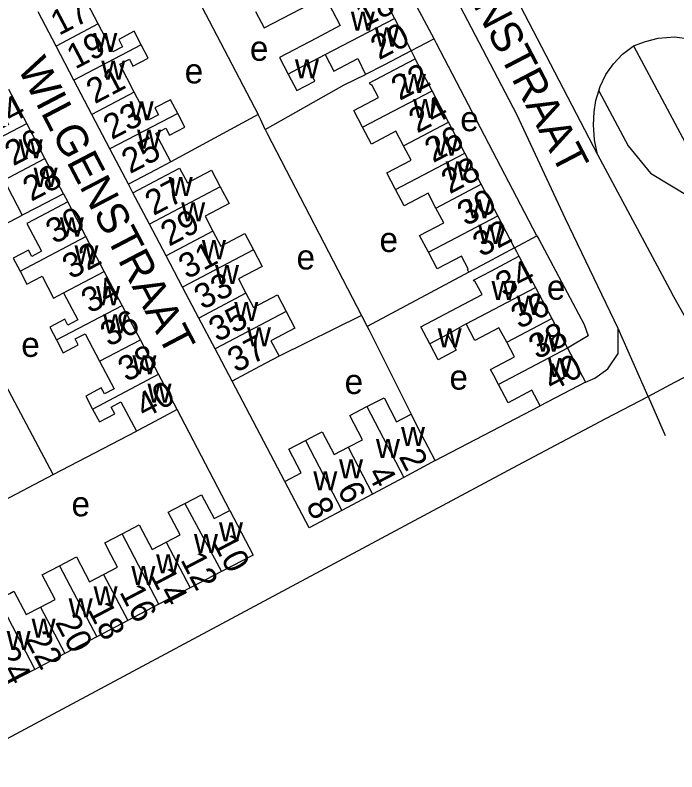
# Model space of a CAD drawing. Extents: x 158356 to 159894, y 383831 to 385260.
# Drawn here: x 159379.2 to 159485.7, y 384265.1 to 384387 of the extents above; entities that cross this region are included whole.
import ezdxf

# ---------------------------------------------------------------- set-up
doc = ezdxf.new("R2010")
doc.units = 0
for name, color, linetype in [('BLT_Basislijn', 7, 'Continuous'), ('BLT_Bebouwing', 7, 'Continuous'), ('BLT_Centroide', 7, 'Continuous'), ('BLT_Huisnummer', 7, 'Continuous'), ('BLT_Huisnummer_ tussenligend', 7, 'Continuous'), ('BLT_Onderverdeling_panden', 7, 'Continuous'), ('BLT_Straatnaam', 7, 'Continuous'), ('BLT_Vlakafsluiter', 7, 'Continuous')]:
    doc.layers.add(name, color=color, linetype=linetype)

msp = doc.modelspace()

# ---------------------------------------------------------------- linework, layer by layer
at = {"layer": 'BLT_Basislijn'}
for p, q in [((159446.66, 384383.13), (159442.98, 384381.23)), ((159478.78, 384382.01), (159487.1, 384366.47)), ((159442.98, 384381.23), (159443.63, 384379.92)), ((159418.33, 384370.96), (159404.29, 384363.33)), ((159398.17, 384358.36), (159397.45, 384359.74)), ((159386.98, 384358.21), (159387.68, 384356.87)), ((159366.92, 384347.68), (159380.36, 384354.74)), ((159459.62, 384349.47), (159463.22, 384351.41)), ((159459.62, 384349.47), (159459.91, 384348.91)), ((159459.91, 384348.91), (159460.33, 384348.14)), ((159452.24, 384345.59), (159435.89, 384336.82)), ((159434.96, 384338.58), (159421.72, 384332.02)), ((159434.96, 384338.58), (159435.89, 384336.82)), ((159485.42, 384327.84), (159493.7, 384332.21)), ((159422.61, 384311.87), (159414.14, 384328.02)), ((159446.84, 384315.22), (159463.76, 384324.01)), ((159413.77, 384307.19), (159405.3, 384323.43)), ((159385.33, 384312.96), (159398.73, 384319.97)), ((159423.05, 384294.6), (159460.13, 384314.46)), ((159371.64, 384305.8), (159385.33, 384312.96)), ((159367.92, 384265.07), (159423.05, 384294.6))]:
    msp.add_line(p, q, dxfattribs=at)
for points in [[(159476.29, 384336.47), (159467.84, 384354.16), (159459.96, 384370.94), (159444.22, 384401.18), (159439.12, 384409.82), (159405.78, 384459.91), (159379.56, 384494.51), (159361.43, 384512.52)], [(159446.66, 384383.13), (159439.98, 384395.74), (159434.84, 384404.77), (159434.31, 384405.59)], [(159408.42, 384390.03), (159408.65, 384389.59), (159418.33, 384370.96)], [(159478.78, 384382.01), (159480.69, 384382.71), (159482.75, 384383.26), (159485.41, 384383.46), (159487.73, 384383.17), (159490.35, 384382.47), (159493.66, 384380.96), (159534.17, 384359.27)], [(159463.22, 384351.41), (159447.05, 384382.38), (159446.66, 384383.13)], [(159473.16, 384374.75), (159473.38, 384375.49), (159474.32, 384377.4), (159475.56, 384379.13), (159476.99, 384380.7), (159478.69, 384381.98), (159478.78, 384382.01)], [(159419.48, 384368.57), (159432.2, 384375.73), (159435.63, 384377.4)], [(159472.97, 384364.5), (159472.47, 384366.87), (159472.31, 384369.29), (159472.41, 384371.42), (159472.73, 384373.24), (159473.16, 384374.75)], [(159473.16, 384374.75), (159477.91, 384365.91), (159481.52, 384361.49), (159488.02, 384357.59)], [(159419.48, 384368.57), (159418.76, 384370.12), (159418.33, 384370.96)], [(159419.48, 384368.57), (159419.78, 384367.92), (159434.96, 384338.58)], [(159472.97, 384364.5), (159484.97, 384342.1)], [(159463.22, 384351.41), (159463.51, 384350.86), (159470.83, 384337.11), (159471.45, 384335.29), (159468.16, 384333.32)], [(159385.33, 384312.96), (159367.27, 384347.02), (159366.92, 384347.68)], [(159491.46, 384336.44), (159488.92, 384335.09), (159484.97, 384342.1)], [(159435.89, 384336.82), (159436.15, 384336.33), (159442.96, 384322.7)], [(159472.53, 384328.48), (159474.64, 384329.97), (159476.29, 384332.49), (159476.29, 384336.47)], [(159471.04, 384327.86), (159472.53, 384328.48)], [(159481.11, 384325.55), (159485.42, 384327.84)], [(159474.33, 384321.97), (159481.11, 384325.55)], [(159460.13, 384314.46), (159474.33, 384321.97)]]:
    msp.add_lwpolyline(points, dxfattribs=at)
at = {"layer": 'BLT_Bebouwing'}
for p, q in [((159437.65, 384391.47), (159440.27, 384386.42)), ((159385.8, 384381.99), (159382.9, 384387.52)), ((159440.27, 384386.42), (159442.98, 384381.23)), ((159388.66, 384376.52), (159385.8, 384381.99)), ((159446.33, 384374.78), (159443.63, 384379.92)), ((159391.56, 384370.99), (159388.66, 384376.52)), ((159381.07, 384369.5), (159378.18, 384375)), ((159448.97, 384369.75), (159446.33, 384374.78)), ((159394.47, 384365.43), (159391.56, 384370.99)), ((159384.02, 384363.87), (159381.07, 384369.5)), ((159451.59, 384364.76), (159448.97, 384369.75)), ((159397.45, 384359.74), (159394.47, 384365.43)), ((159386.98, 384358.21), (159384.02, 384363.87)), ((159454.24, 384359.72), (159451.59, 384364.76)), ((159456.9, 384354.65), (159454.24, 384359.72)), ((159400.83, 384353.3), (159398.17, 384358.36)), ((159390.6, 384351.32), (159387.68, 384356.87)), ((159459.62, 384349.47), (159456.9, 384354.65)), ((159403.52, 384348.19), (159400.83, 384353.3)), ((159393.57, 384345.69), (159390.6, 384351.32)), ((159406.18, 384343.13), (159403.52, 384348.19)), ((159460.33, 384348.14), (159462.98, 384343.11)), ((159396.45, 384340.21), (159393.57, 384345.69)), ((159408.79, 384338.18), (159406.18, 384343.13)), ((159462.98, 384343.11), (159465.62, 384338.11)), ((159399.37, 384334.68), (159396.45, 384340.21)), ((159411.41, 384333.2), (159408.79, 384338.18)), ((159465.62, 384338.11), (159468.16, 384333.32)), ((159402.3, 384329.12), (159399.37, 384334.68)), ((159468.16, 384333.32), (159471.04, 384327.86)), ((159414.14, 384328.02), (159411.41, 384333.2)), ((159405.3, 384323.43), (159402.3, 384329.12)), ((159471.04, 384327.86), (159463.76, 384324.01)), ((159446.84, 384315.22), (159441.77, 384312.51)), ((159441.77, 384312.51), (159436.76, 384309.83)), ((159436.76, 384309.83), (159431.81, 384307.19)), ((159412.46, 384297.35), (159407.39, 384294.7)), ((159407.39, 384294.7), (159402.37, 384292.07)), ((159402.37, 384292.07), (159397.35, 384289.44)), ((159397.35, 384289.44), (159392.34, 384286.82)), ((159392.34, 384286.82), (159387.24, 384284.15)), ((159387.24, 384284.15), (159382.36, 384281.59))]:
    msp.add_line(p, q, dxfattribs=at)
for points in [[(159392.59, 384385.55), (159390.25, 384390.02), (159391.77, 384390.81), (159392.32, 384389.77), (159394.8, 384391.07), (159393.7, 384393.17)], [(159417.9, 384387.57), (159419.29, 384384.91), (159425.21, 384388), (159429.08, 384390.02), (159430.32, 384387.65)], [(159430.32, 384387.65), (159431.55, 384385.28), (159427.73, 384383.28), (159421.76, 384380.17), (159423.17, 384377.46)], [(159399.52, 384382.21), (159398.39, 384384.37), (159395.89, 384383.06), (159396.5, 384381.89), (159394.94, 384381.07), (159392.59, 384385.55)], [(159398.4, 384374.57), (159396.06, 384379.05), (159397.6, 384379.86), (159398.17, 384378.75), (159400.65, 384380.05), (159399.52, 384382.21)], [(159442.98, 384381.23), (159438.55, 384378.92), (159435.63, 384377.4)], [(159426.18, 384379.06), (159429.12, 384380.61)], [(159429.12, 384380.61), (159430.51, 384377.94), (159434.41, 384379.97), (159435.63, 384377.4)], [(159435.15, 384368.91), (159433.73, 384371.61), (159437.71, 384373.7), (159436.63, 384375.76), (159436.46, 384375.67), (159436.26, 384376.05), (159439.21, 384377.6), (159443.63, 384379.92)], [(159423.17, 384377.46), (159424.54, 384374.83), (159427.44, 384376.34), (159426.18, 384379.06)], [(159405.38, 384371.15), (159404.23, 384373.35), (159401.72, 384372.04), (159402.31, 384370.92), (159400.74, 384370.1), (159398.4, 384374.57)], [(159404.29, 384363.33), (159401.88, 384367.93), (159403.46, 384368.76), (159404.05, 384367.64), (159406.53, 384368.95), (159405.38, 384371.15)], [(159441.72, 384365.94), (159440.5, 384368.28), (159436.57, 384366.21), (159435.15, 384368.91)], [(159440.43, 384358.9), (159439.04, 384361.56), (159442.95, 384363.61), (159441.72, 384365.94)], [(159404.29, 384363.33), (159401.88, 384362.06), (159397.45, 384359.74)], [(159398.17, 384358.36), (159402.59, 384360.69), (159405.7, 384362.32), (159406.95, 384359.95), (159410.83, 384361.99), (159412.24, 384359.3)], [(159373.35, 384358.28), (159374.46, 384356.16), (159377, 384357.49), (159376.41, 384358.62), (159377.92, 384359.41), (159380.36, 384354.74)], [(159412.24, 384359.3), (159413.66, 384356.61), (159409.78, 384354.57), (159411.05, 384352.16)], [(159446.96, 384355.9), (159445.71, 384358.29), (159441.83, 384356.24), (159440.43, 384358.9)], [(159386.98, 384358.21), (159382.56, 384355.89), (159380.36, 384354.74)], [(159387.68, 384356.87), (159383.25, 384354.54), (159381.12, 384353.42), (159383.48, 384348.95), (159381.88, 384348.11), (159381.35, 384349.11), (159378.9, 384347.82), (159380, 384345.73)], [(159445.74, 384348.79), (159444.33, 384351.48), (159448.21, 384353.52), (159446.96, 384355.9)], [(159411.05, 384352.16), (159412.32, 384349.74), (159416.21, 384351.79), (159417.61, 384349.14)], [(159417.61, 384349.14), (159419, 384346.5), (159415.16, 384344.48), (159416.38, 384342.17)], [(159459.62, 384349.47), (159455.19, 384347.14), (159452.24, 384345.59)], [(159445.98, 384334), (159444.53, 384336.74), (159450.43, 384339.86), (159454.38, 384341.95), (159453.24, 384344.1), (159453.12, 384344.04), (159453, 384344.26), (159455.91, 384345.8), (159460.33, 384348.14)], [(159452.24, 384345.59), (159452.03, 384345.99), (159452.17, 384346.08), (159451.08, 384348.17), (159447.15, 384346.11), (159445.74, 384348.79)], [(159380, 384345.73), (159381.1, 384343.65), (159383.54, 384344.93), (159385.41, 384341.39), (159387.02, 384342.24)], [(159387.02, 384342.24), (159389.3, 384337.9), (159387.69, 384337.05), (159387.21, 384337.97), (159384.79, 384336.69), (159385.87, 384334.64)], [(159416.38, 384342.17), (159417.59, 384339.87), (159421.43, 384341.89), (159422.84, 384339.22)], [(159422.84, 384339.22), (159424.25, 384336.54), (159420.4, 384334.52), (159421.72, 384332.02)], [(159451.83, 384337.22), (159448.83, 384335.55)], [(159458.36, 384334.27), (159457.11, 384336.62), (159453.23, 384334.57), (159451.83, 384337.22)], [(159385.87, 384334.64), (159386.95, 384332.59), (159389.38, 384333.87), (159388.88, 384334.82), (159390.47, 384335.66), (159392.81, 384331.22)], [(159448.83, 384335.55), (159450.21, 384332.98), (159447.33, 384331.45), (159445.98, 384334)], [(159457.05, 384327.45), (159456.26, 384328.94), (159455.76, 384329.88), (159459.6, 384331.91), (159458.36, 384334.27)], [(159421.72, 384332.02), (159418.56, 384330.35), (159414.14, 384328.02)], [(159392.81, 384331.22), (159395.15, 384326.79), (159393.58, 384325.96), (159393.08, 384326.91), (159390.59, 384325.6), (159391.68, 384323.52)], [(159463.76, 384324.01), (159462.42, 384326.54), (159458.6, 384324.52), (159457.05, 384327.45)], [(159435.85, 384323.92), (159438.62, 384325.35), (159440.62, 384321.48), (159442.96, 384322.7)], [(159391.68, 384323.52), (159392.77, 384321.45), (159395.26, 384322.75), (159394.68, 384323.84), (159396.25, 384324.67), (159398.73, 384319.97)], [(159432.84, 384317.39), (159435.12, 384318.57), (159433.09, 384322.48), (159435.85, 384323.92)], [(159405.3, 384323.43), (159400.88, 384321.1), (159398.73, 384319.97)], [(159446.84, 384315.22), (159444.6, 384319.54), (159442.96, 384322.7)], [(159425.96, 384318.47), (159427.7, 384319.38), (159428.65, 384319.87), (159430.56, 384316.2), (159432.84, 384317.39)], [(159422.61, 384311.87), (159425.25, 384313.24), (159423.26, 384317.07), (159425.96, 384318.47)], [(159431.81, 384307.19), (159426.55, 384304.38), (159422.61, 384311.87)], [(159406.53, 384308.32), (159409.21, 384309.72), (159411.23, 384305.86), (159413.77, 384307.19)], [(159403.54, 384302.05), (159405.79, 384303.23), (159403.86, 384306.92), (159404.78, 384307.4), (159406.53, 384308.32)], [(159413.77, 384307.19), (159417.53, 384300), (159412.46, 384297.35)], [(159396.43, 384303.4), (159399.2, 384304.84), (159401.28, 384300.87), (159403.54, 384302.05)], [(159393.46, 384296.87), (159395.71, 384298.05), (159394.69, 384300), (159393.67, 384301.95), (159396.43, 384303.4)], [(159386.34, 384298.28), (159389.1, 384299.73), (159391.21, 384295.69), (159393.46, 384296.87)], [(159383.32, 384291.62), (159385.66, 384292.85), (159383.58, 384296.83), (159386.34, 384298.28)], [(159376.47, 384292.83), (159378.37, 384293.82), (159379.01, 384294.16), (159380.99, 384290.4), (159383.32, 384291.62)], [(159382.36, 384281.59), (159377.19, 384278.88), (159373.34, 384286.22)]]:
    msp.add_lwpolyline(points, dxfattribs=at)
at = {"layer": 'BLT_Onderverdeling_panden'}
for p, q in [((159429.12, 384380.61), (159440.27, 384386.42)), ((159392.59, 384385.55), (159385.8, 384381.99)), ((159399.52, 384382.21), (159388.66, 384376.52)), ((159426.18, 384379.06), (159423.17, 384377.46)), ((159435.15, 384368.91), (159446.33, 384374.78)), ((159398.4, 384374.57), (159391.56, 384370.99)), ((159405.38, 384371.15), (159394.47, 384365.43)), ((159374.46, 384366.03), (159381.07, 384369.5)), ((159441.72, 384365.94), (159448.97, 384369.75)), ((159373.35, 384358.28), (159384.02, 384363.87)), ((159440.43, 384358.9), (159451.59, 384364.76)), ((159412.24, 384359.3), (159400.83, 384353.3)), ((159446.96, 384355.9), (159454.24, 384359.72)), ((159445.74, 384348.79), (159456.9, 384354.65)), ((159411.05, 384352.16), (159403.52, 384348.19)), ((159380, 384345.73), (159390.6, 384351.32)), ((159417.61, 384349.14), (159406.18, 384343.13)), ((159387.02, 384342.24), (159393.57, 384345.69)), ((159451.83, 384337.22), (159462.98, 384343.11)), ((159416.38, 384342.17), (159408.79, 384338.18)), ((159385.87, 384334.64), (159396.45, 384340.21)), ((159422.84, 384339.22), (159411.41, 384333.2)), ((159458.36, 384334.27), (159465.62, 384338.11)), ((159392.81, 384331.22), (159399.37, 384334.68)), ((159448.83, 384335.55), (159445.98, 384334)), ((159468.16, 384333.32), (159457.05, 384327.45)), ((159391.68, 384323.52), (159402.3, 384329.12)), ((159435.85, 384323.92), (159441.77, 384312.51)), ((159425.96, 384318.47), (159431.81, 384307.19)), ((159432.84, 384317.39), (159436.76, 384309.83)), ((159406.53, 384308.32), (159412.46, 384297.35)), ((159402.37, 384292.07), (159396.43, 384303.4)), ((159403.54, 384302.05), (159407.39, 384294.7)), ((159386.34, 384298.28), (159392.34, 384286.82)), ((159393.46, 384296.87), (159397.35, 384289.44)), ((159376.47, 384292.83), (159382.36, 384281.59)), ((159383.32, 384291.62), (159387.24, 384284.15))]:
    msp.add_line(p, q, dxfattribs=at)
at = {"layer": 'BLT_Vlakafsluiter'}
for p, q in [((159457.18, 384394.95), (159472.97, 384364.5)), ((159481.11, 384325.55), (159476.29, 384336.47)), ((159481.11, 384325.55), (159483.88, 384319.27))]:
    msp.add_line(p, q, dxfattribs=at)

# ---------------------------------------------------------------- texts
at = {"layer": 'BLT_Centroide'}
for s, p in [('w', (159433.26, 384384.47)), ('w', (159437.12, 384381.91)), ('w', (159391.79, 384381.03)), ('e', (159417.01, 384379.62)), ('w', (159393.08, 384376.59)), ('w', (159424.26, 384376.79)), ('e', (159406.51, 384375.97)), ('w', (159441.48, 384374.41)), ('w', (159443.29, 384370.38)), ('w', (159397.64, 384370)), ('e', (159450.88, 384368.27)), ('w', (159398.84, 384365.44)), ('w', (159446.67, 384364.31)), ('w', (159379.79, 384363.88)), ('w', (159448.54, 384360.34)), ('w', (159382.19, 384359.31)), ('w', (159403.93, 384357.81)), ('w', (159405.95, 384353.75)), ('w', (159451.98, 384354.25)), ('w', (159386.4, 384351.31)), ('w', (159453.77, 384350.12)), ('e', (159437.88, 384348.81)), ('w', (159409.28, 384347.66)), ('w', (159388.77, 384346.84)), ('e', (159424.52, 384346)), ('w', (159411.39, 384343.66)), ('e', (159464.82, 384341.12)), ('w', (159392.25, 384340.25)), ('w', (159455.91, 384341.06)), ('w', (159459.96, 384338.69)), ('w', (159414.49, 384337.69)), ('w', (159393.38, 384335.72)), ('w', (159416.54, 384333.62)), ('w', (159447.24, 384333.45)), ('w', (159463.13, 384332.78)), ('e', (159380.2, 384331.92)), ('w', (159398.09, 384329.09)), ('w', (159464.98, 384328.66)), ('e', (159449.14, 384326.64)), ('e', (159432.26, 384325.94)), ('w', (159400.52, 384324.53)), ('w', (159441.34, 384317.58)), ('w', (159437.3, 384315.62)), ('w', (159431.36, 384312.34)), ('w', (159427.22, 384310.41)), ('e', (159388.29, 384306.24)), ('w', (159412.03, 384302.2)), ('w', (159408, 384300.31)), ('w', (159401.91, 384297.06)), ('w', (159397.92, 384295.16)), ('w', (159391.84, 384291.89)), ('w', (159387.83, 384289.95)), ('w', (159381.86, 384286.7)), ('w', (159377.84, 384284.72))]:
    msp.add_text(s, height=4, dxfattribs=at).set_placement(p)
at = {"layer": 'BLT_Huisnummer'}
for s, rotation, p in [('20', 27.5165, (159437.79, 384379.67)), ('19', 27.6378, (159388.88, 384378.18)), ('22', 27.5165, (159441.11, 384373.13)), ('26', 27.5165, (159446.5, 384363.11)), ('25', 27.6378, (159397.71, 384361.34)), ('28', 27.6582, (159381.8, 384356.88)), ('27', 27.6378, (159401.48, 384354.6)), ('30', 27.6582, (159385.51, 384350.01)), ('32', 27.5165, (159454.24, 384347.94)), ('31', 27.6378, (159406.88, 384344.37)), ('34', 27.5165, (159457.91, 384341.47)), ('34', 27.6582, (159391.22, 384338.84)), ('37', 27.6378, (159414.76, 384329.3)), ('38', 27.6582, (159397.13, 384327.81)), ('40', 27.8615, (159465.66, 384326.31)), ('40', 27.6582, (159400.01, 384321.95)), ('2', 297.4265, (159440.92, 384315.87)), ('8', 297.7708, (159425.94, 384308.01)), ('10', 297.6509, (159410.89, 384302.1)), ('14', 297.6509, (159400.89, 384296.72)), ('18', 297.6509, (159390.81, 384291.21)), ('24', 297.6509, (159375.72, 384284.05))]:
    msp.add_text(s, height=4, rotation=rotation, dxfattribs=at).set_placement(p)
at = {"layer": 'BLT_Huisnummer_ tussenligend'}
for s, rotation, p in [('18', 27.5165, (159435.39, 384384.89)), ('17', 27.6378, (159386.27, 384383.61)), ('21', 27.6378, (159392.03, 384372.6)), ('24', 27.6582, (159375.89, 384368.05)), ('24', 27.5165, (159443.93, 384367.87)), ('23', 27.6378, (159394.76, 384366.83)), ('26', 27.6582, (159378.9, 384362.6)), ('28', 27.5165, (159449.17, 384358.09)), ('30', 27.5165, (159451.75, 384352.9)), ('29', 27.6378, (159404, 384349.65)), ('32', 27.6582, (159388.18, 384344.35)), ('33', 27.6378, (159409.39, 384339.44)), ('36', 27.5165, (159460.39, 384336.33)), ('36', 27.6582, (159394.29, 384333.47)), ('35', 27.6378, (159411.75, 384334.24)), ('38', 27.5165, (159463.24, 384331.43)), ('4', 297.4265, (159435.84, 384313.16)), ('6', 297.4265, (159430.99, 384310.56)), ('12', 297.6509, (159405.76, 384299.25)), ('16', 297.6509, (159395.93, 384294.06)), ('20', 297.6509, (159385.59, 384289.16)), ('22', 297.6509, (159380.75, 384286.49))]:
    msp.add_text(s, height=4, rotation=rotation, dxfattribs=at).set_placement(p)
at = {"layer": 'BLT_Straatnaam'}
for s, rotation, p in [('ZWAANSTRAAT', 297.4949, (159443.97, 384405.78)), ('WILGENSTRAAT', 297.6137, (159379.5, 384378.51))]:
    msp.add_text(s, height=5, rotation=rotation, dxfattribs=at).set_placement(p)

doc.saveas('drawing.dxf')
